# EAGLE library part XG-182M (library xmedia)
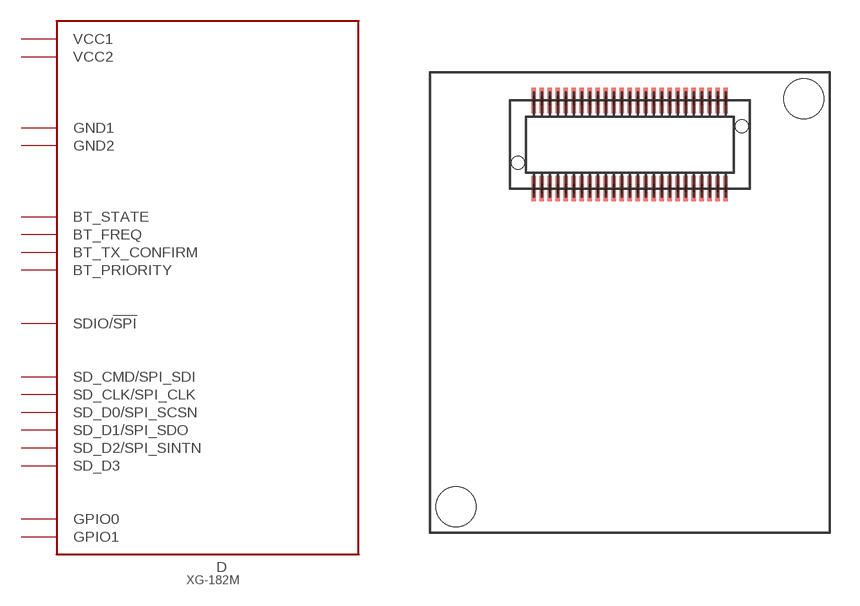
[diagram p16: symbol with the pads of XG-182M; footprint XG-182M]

Designator prefix D

## XG-182M  [XG-182M]
P$1  GND1  sup
P$2  BT_STATE
P$3  BT_FREQ
P$4  BT_TX_CONFIRM
P$5  BT_PRIORITY
P$9  SD_CMD/SPI_SDI
P$10  SD_D2/SPI_SINTN
P$13  VCC1  sup
P$25  SD_D0/SPI_SCSN
P$32  SD_CLK/SPI_CLK
P$34  SD_D1/SPI_SDO
P$35  SD_D3
P$38  VCC2  sup
P$39  GPIO0
P$46  GPIO1
P$49  SDIO/!SPI
P$50  GND2  sup

## Footprint XG-182M (pad centres in mm)
smd 0.203 x 1.27: P$1 4.8,-2.2; P$2 4.4,-2.2; P$3 4,-2.2; P$4 3.6,-2.2; P$5 3.2,-2.2; P$6 2.8,-2.2; P$7 2.4,-2.2; P$8 2,-2.2; P$9 1.6,-2.2; P$10 1.2,-2.2; P$11 0.8,-2.2; P$12 0.4,-2.2; P$13 0,-2.2; P$14 -0.4,-2.2; P$15 -0.8,-2.2; P$16 -1.2,-2.2; P$17 -1.6,-2.2; P$18 -2,-2.2; P$19 -2.4,-2.2; P$20 -2.8,-2.2; P$21 -3.2,-2.2; P$22 -3.6,-2.2; P$23 -4,-2.2; P$24 -4.4,-2.2; P$25 -4.8,-2.2; P$26 -4.8,2.2; P$27 -4.4,2.2; P$28 -4,2.2; P$29 -3.6,2.2; P$30 -3.2,2.2; P$31 -2.8,2.2; P$32 -2.4,2.2; P$33 -2,2.2; P$34 -1.6,2.2; P$35 -1.2,2.2; P$36 -0.8,2.2; P$37 -0.4,2.2; P$38 0,2.2; P$39 0.4,2.2; P$40 0.8,2.2; P$41 1.2,2.2; P$42 1.6,2.2; P$43 2,2.2; P$44 2.4,2.2; P$45 2.8,2.2; P$46 3.2,2.2; P$47 3.6,2.2; P$48 4,2.2; P$49 4.4,2.2; P$50 4.8,2.2
hole 0.65 at 5.6,0.9
hole 0.65 at -5.6,-0.9
hole 2 at -8.7,-18.1
hole 2 at 8.7,2.3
